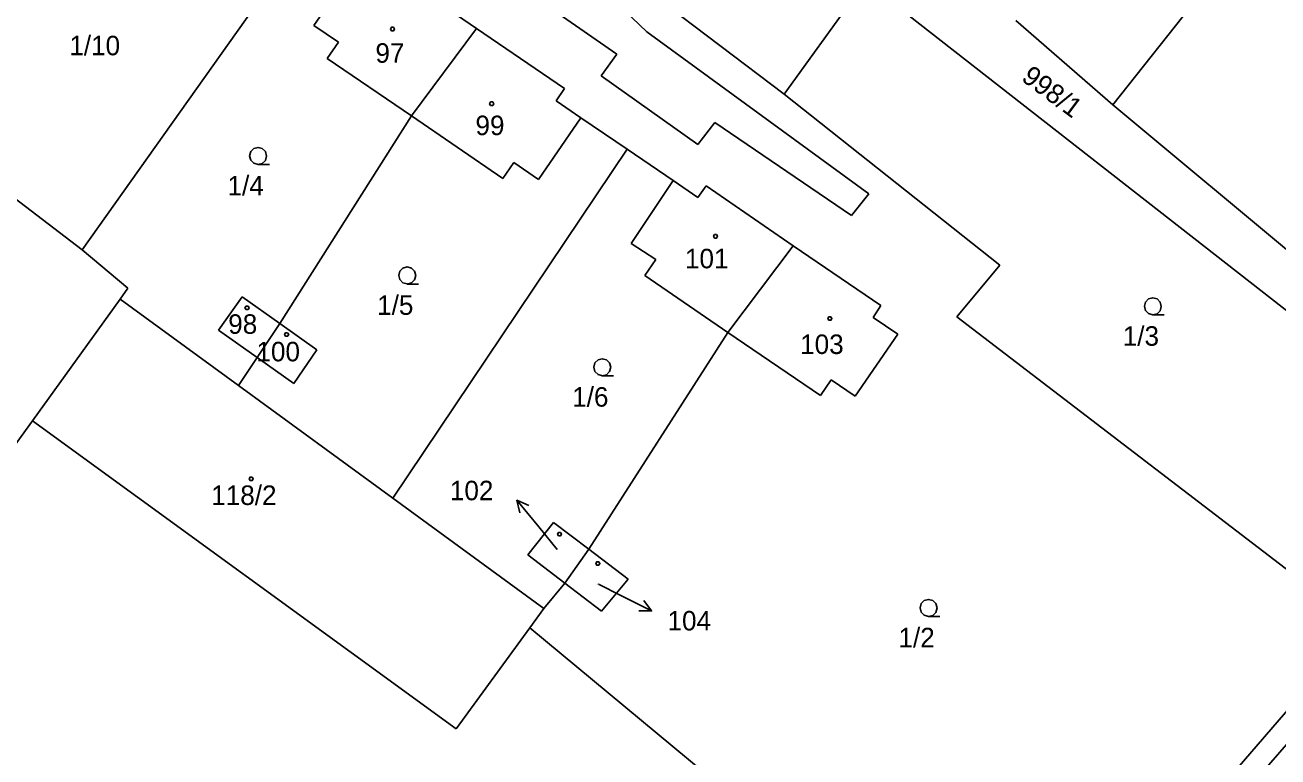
# Model space of a CAD drawing. Extents: x -852001 to -842497, y -1063614 to -1052182.
# Drawn here: x -849296.3 to -849187.1, y -1056403.5 to -1056339.7 of the extents above; entities that cross this region are included whole.
import ezdxf

# ---------------------------------------------------------------- set-up
doc = ezdxf.new("R2010")
doc.units = 0
for name, color, linetype in [('Default', 7, 'Continuous'), ('KN_HRANICE', 7, 'Continuous'), ('KN_KULTURY', 7, 'Continuous'), ('KN_PARCELY', 7, 'Continuous')]:
    doc.layers.add(name, color=color, linetype=linetype)

# ---------------------------------------------------------------- blocks, each defined once
blk = doc.blocks.new('304')
at = {"layer": 'Default'}
blk.add_lwpolyline([(0, 0), (-0.38, 0.1), (-0.65, 0.37), (-0.75, 0.74), (-0.65, 1.11), (-0.38, 1.38), (-0.01, 1.48), (0.36, 1.38), (0.63, 1.11), (0.73, 0.73), (0.63, 0.35), (0.36, 0.08), (-0.02, -0.02), (0.98, -0.02)], dxfattribs=at)
blk = doc.blocks.new('NAHRADNI_SYMBOL')
at = {"layer": 'Default'}
blk.add_lwpolyline([(0.09, 0.15), (0.18, 0), (0.09, -0.15), (-0.09, -0.15), (-0.18, 0), (-0.09, 0.15), (0.09, 0.15)], dxfattribs=at)
blk = doc.blocks.new('10292')
at = {"layer": 'Default'}
blk.add_line((0, 3), (0, 0), dxfattribs=at)
blk.add_lwpolyline([(-0.5, 2), (0, 3), (0.5, 2)], dxfattribs=at)
blk = doc.blocks.new('402')
at = {"layer": 'Default'}
blk.add_lwpolyline([(0.09, 0.15), (0.18, 0), (0.09, -0.15), (-0.09, -0.15), (-0.18, 0), (-0.09, 0.15), (0.09, 0.15)], dxfattribs=at)

msp = doc.modelspace()

# ---------------------------------------------------------------- linework, layer by layer
at = {"layer": 'KN_HRANICE'}
for p, q in [((-849201.5, -1056346.7), (-849181.26, -1056321.09)), ((-849201.5, -1056346.7), (-849181.26, -1056321.09)), ((-849291.34, -1056359.34), (-849271.64, -1056331.55)), ((-849291.34, -1056359.34), (-849271.64, -1056331.55)), ((-849244.73, -1056342.28), (-849259.75, -1056331.81)), ((-849244.73, -1056342.28), (-849259.75, -1056331.81)), ((-849267.48, -1056334.39), (-849271.16, -1056339.78)), ((-849267.48, -1056334.39), (-849271.16, -1056339.78)), ((-849249.23, -1056333.55), (-849242.11, -1056340.33)), ((-849249.23, -1056333.55), (-849242.11, -1056340.33)), ((-849230.16, -1056345.77), (-849246.19, -1056333.59)), ((-849230.16, -1056345.77), (-849246.19, -1056333.59)), ((-849264.6, -1056334.81), (-849256.96, -1056340.03)), ((-849264.6, -1056334.81), (-849256.96, -1056340.03)), ((-849223.07, -1056335.94), (-849230.16, -1056345.77)), ((-849223.07, -1056335.94), (-849230.16, -1056345.77)), ((-849223.07, -1056335.94), (-849168.88, -1056378.32)), ((-849223.07, -1056335.94), (-849168.88, -1056378.32)), ((-849271.16, -1056339.78), (-849269.01, -1056341.24)), ((-849271.16, -1056339.78), (-849269.01, -1056341.24)), ((-849201.5, -1056346.7), (-849209.96, -1056339.35)), ((-849201.5, -1056346.7), (-849209.96, -1056339.35)), ((-849262.65, -1056347.66), (-849256.96, -1056340.03)), ((-849262.65, -1056347.66), (-849256.96, -1056340.03)), ((-849256.96, -1056340.03), (-849249.3, -1056345.26)), ((-849256.96, -1056340.03), (-849249.3, -1056345.26)), ((-849242.11, -1056340.33), (-849222.76, -1056354.44)), ((-849242.11, -1056340.33), (-849222.76, -1056354.44)), ((-849269.01, -1056341.24), (-849269.98, -1056342.65)), ((-849269.01, -1056341.24), (-849269.98, -1056342.65)), ((-849269.98, -1056342.65), (-849262.65, -1056347.66)), ((-849269.98, -1056342.65), (-849262.65, -1056347.66)), ((-849246.11, -1056344.16), (-849244.73, -1056342.28)), ((-849246.11, -1056344.16), (-849244.73, -1056342.28)), ((-849237.68, -1056350.14), (-849246.11, -1056344.16)), ((-849237.68, -1056350.14), (-849246.11, -1056344.16)), ((-849250.02, -1056346.33), (-849249.3, -1056345.26)), ((-849250.02, -1056346.33), (-849249.3, -1056345.26)), ((-849247.87, -1056347.82), (-849250.02, -1056346.33)), ((-849247.87, -1056347.82), (-849250.02, -1056346.33)), ((-849230.16, -1056345.77), (-849211.36, -1056360.66)), ((-849230.16, -1056345.77), (-849211.36, -1056360.66)), ((-849201.5, -1056346.7), (-849166.49, -1056375.89)), ((-849201.5, -1056346.7), (-849166.49, -1056375.89)), ((-849262.65, -1056347.66), (-849274.12, -1056365.74)), ((-849262.65, -1056347.66), (-849274.12, -1056365.74)), ((-849262.65, -1056347.66), (-849254.67, -1056353.12)), ((-849262.65, -1056347.66), (-849254.67, -1056353.12)), ((-849251.57, -1056353.21), (-849247.87, -1056347.82)), ((-849251.57, -1056353.21), (-849247.87, -1056347.82)), ((-849243.84, -1056350.56), (-849247.87, -1056347.82)), ((-849243.84, -1056350.56), (-849247.87, -1056347.82)), ((-849236.2, -1056348.24), (-849237.68, -1056350.14)), ((-849236.2, -1056348.24), (-849237.68, -1056350.14)), ((-849224.27, -1056356.34), (-849236.2, -1056348.24)), ((-849224.27, -1056356.34), (-849236.2, -1056348.24)), ((-849264.25, -1056380.97), (-849243.84, -1056350.56)), ((-849264.25, -1056380.97), (-849243.84, -1056350.56)), ((-849243.84, -1056350.56), (-849239.82, -1056353.29)), ((-849243.84, -1056350.56), (-849239.82, -1056353.29)), ((-849254.67, -1056353.12), (-849253.72, -1056351.73)), ((-849254.67, -1056353.12), (-849253.72, -1056351.73)), ((-849253.72, -1056351.73), (-849251.57, -1056353.21)), ((-849253.72, -1056351.73), (-849251.57, -1056353.21)), ((-849291.34, -1056359.34), (-849299.09, -1056353.44)), ((-849291.34, -1056359.34), (-849299.09, -1056353.44)), ((-849239.82, -1056353.29), (-849243.49, -1056358.79)), ((-849239.82, -1056353.29), (-849243.49, -1056358.79)), ((-849237.67, -1056354.78), (-849239.82, -1056353.29)), ((-849237.67, -1056354.78), (-849239.82, -1056353.29)), ((-849236.96, -1056353.76), (-849237.67, -1056354.78)), ((-849236.96, -1056353.76), (-849237.67, -1056354.78)), ((-849229.36, -1056358.98), (-849236.96, -1056353.76)), ((-849229.36, -1056358.98), (-849236.96, -1056353.76)), ((-849222.76, -1056354.44), (-849224.27, -1056356.34)), ((-849222.76, -1056354.44), (-849224.27, -1056356.34)), ((-849287.35, -1056362.68), (-849291.34, -1056359.34)), ((-849287.35, -1056362.68), (-849291.34, -1056359.34)), ((-849243.49, -1056358.79), (-849241.35, -1056360.18)), ((-849243.49, -1056358.79), (-849241.35, -1056360.18)), ((-849235.05, -1056366.54), (-849229.36, -1056358.98)), ((-849235.05, -1056366.54), (-849229.36, -1056358.98)), ((-849221.74, -1056364.19), (-849229.36, -1056358.98)), ((-849221.74, -1056364.19), (-849229.36, -1056358.98)), ((-849241.35, -1056360.18), (-849242.29, -1056361.57)), ((-849241.35, -1056360.18), (-849242.29, -1056361.57)), ((-849211.36, -1056360.66), (-849215.1, -1056365.17)), ((-849211.36, -1056360.66), (-849215.1, -1056365.17)), ((-849242.29, -1056361.57), (-849235.05, -1056366.54)), ((-849242.29, -1056361.57), (-849235.05, -1056366.54)), ((-849288.04, -1056363.64), (-849287.35, -1056362.68)), ((-849288.04, -1056363.64), (-849287.35, -1056362.68)), ((-849288.04, -1056363.64), (-849295.68, -1056374.24)), ((-849288.04, -1056363.64), (-849295.68, -1056374.24)), ((-849277.71, -1056371.17), (-849288.04, -1056363.64)), ((-849277.71, -1056371.17), (-849288.04, -1056363.64)), ((-849277.39, -1056363.43), (-849279.45, -1056366.33)), ((-849277.39, -1056363.43), (-849279.45, -1056366.33)), ((-849274.12, -1056365.74), (-849277.39, -1056363.43)), ((-849274.12, -1056365.74), (-849277.39, -1056363.43)), ((-849221.74, -1056364.19), (-849222.41, -1056365.22)), ((-849221.74, -1056364.19), (-849222.41, -1056365.22)), ((-849274.12, -1056365.74), (-849276.09, -1056368.72)), ((-849274.12, -1056365.74), (-849276.09, -1056368.72)), ((-849270.88, -1056368.05), (-849274.12, -1056365.74)), ((-849270.88, -1056368.05), (-849274.12, -1056365.74)), ((-849222.41, -1056365.22), (-849220.26, -1056366.67)), ((-849222.41, -1056365.22), (-849220.26, -1056366.67)), ((-849215.1, -1056365.17), (-849179.95, -1056392.09)), ((-849215.1, -1056365.17), (-849179.95, -1056392.09)), ((-849279.45, -1056366.33), (-849276.09, -1056368.72)), ((-849279.45, -1056366.33), (-849276.09, -1056368.72)), ((-849235.05, -1056366.54), (-849247.17, -1056385.43)), ((-849235.05, -1056366.54), (-849247.17, -1056385.43)), ((-849235.05, -1056366.54), (-849227, -1056372.04)), ((-849235.05, -1056366.54), (-849227, -1056372.04)), ((-849220.26, -1056366.67), (-849223.96, -1056372.1)), ((-849220.26, -1056366.67), (-849223.96, -1056372.1)), ((-849272.9, -1056370.99), (-849270.88, -1056368.05)), ((-849272.9, -1056370.99), (-849270.88, -1056368.05)), ((-849276.09, -1056368.72), (-849277.71, -1056371.17)), ((-849276.09, -1056368.72), (-849277.71, -1056371.17)), ((-849276.09, -1056368.72), (-849272.9, -1056370.99)), ((-849276.09, -1056368.72), (-849272.9, -1056370.99)), ((-849264.25, -1056380.97), (-849277.71, -1056371.17)), ((-849264.25, -1056380.97), (-849277.71, -1056371.17)), ((-849226.06, -1056370.67), (-849227, -1056372.04)), ((-849226.06, -1056370.67), (-849227, -1056372.04)), ((-849223.96, -1056372.1), (-849226.06, -1056370.67)), ((-849223.96, -1056372.1), (-849226.06, -1056370.67)), ((-849295.68, -1056374.24), (-849308.52, -1056391.92)), ((-849295.68, -1056374.24), (-849308.52, -1056391.92)), ((-849258.75, -1056401.09), (-849295.68, -1056374.24)), ((-849258.75, -1056401.09), (-849295.68, -1056374.24)), ((-849207.62, -1056426.96), (-849167.05, -1056380.13)), ((-849207.62, -1056426.96), (-849167.05, -1056380.13)), ((-849251.09, -1056390.6), (-849264.25, -1056380.97)), ((-849251.09, -1056390.6), (-849264.25, -1056380.97)), ((-849252.49, -1056385.93), (-849250.27, -1056383.09)), ((-849252.49, -1056385.93), (-849250.27, -1056383.09)), ((-849250.27, -1056383.09), (-849247.17, -1056385.43)), ((-849250.27, -1056383.09), (-849247.17, -1056385.43)), ((-849249.26, -1056388.39), (-849247.17, -1056385.43)), ((-849249.26, -1056388.39), (-849247.17, -1056385.43)), ((-849247.17, -1056385.43), (-849243.74, -1056388.04)), ((-849247.17, -1056385.43), (-849243.74, -1056388.04)), ((-849249.26, -1056388.39), (-849252.49, -1056385.93)), ((-849249.26, -1056388.39), (-849252.49, -1056385.93)), ((-849251.09, -1056390.6), (-849249.26, -1056388.39)), ((-849251.09, -1056390.6), (-849249.26, -1056388.39)), ((-849246.07, -1056390.82), (-849249.26, -1056388.39)), ((-849246.07, -1056390.82), (-849249.26, -1056388.39)), ((-849243.74, -1056388.04), (-849246.07, -1056390.82)), ((-849243.74, -1056388.04), (-849246.07, -1056390.82)), ((-849252.32, -1056392.28), (-849251.09, -1056390.6)), ((-849252.32, -1056392.28), (-849251.09, -1056390.6)), ((-849258.75, -1056401.09), (-849252.32, -1056392.28)), ((-849258.75, -1056401.09), (-849252.32, -1056392.28)), ((-849252.32, -1056392.28), (-849210.21, -1056427.21)), ((-849252.32, -1056392.28), (-849210.21, -1056427.21)), ((-849210.21, -1056427.21), (-849179.95, -1056392.09)), ((-849210.21, -1056427.21), (-849179.95, -1056392.09))]:
    msp.add_line(p, q, dxfattribs=at)
at = {"layer": 'KN_PARCELY'}
for p, q in [((-849249.93, -1056385.45), (-849251.54, -1056383.48)), ((-849249.93, -1056385.45), (-849251.54, -1056383.48)), ((-849246.35, -1056388.48), (-849244.39, -1056389.46)), ((-849246.35, -1056388.48), (-849244.39, -1056389.46))]:
    msp.add_line(p, q, dxfattribs=at)

# ---------------------------------------------------------------- block references
at = {"layer": 'KN_KULTURY'}
for name, p in [('402', (-849264.29, -1056340.08)), ('402', (-849264.29, -1056340.08)), ('402', (-849255.65, -1056346.59)), ('402', (-849255.65, -1056346.59)), ('304', (-849276, -1056351.88)), ('304', (-849276, -1056351.88)), ('402', (-849236.13, -1056358.15)), ('402', (-849236.13, -1056358.15)), ('304', (-849263, -1056362.3)), ('304', (-849263, -1056362.3)), ('304', (-849198.01, -1056364.99)), ('304', (-849198.01, -1056364.99)), ('402', (-849276.97, -1056364.39)), ('402', (-849276.97, -1056364.39)), ('402', (-849226.17, -1056365.32)), ('402', (-849226.17, -1056365.32)), ('402', (-849273.52, -1056366.71)), ('402', (-849273.52, -1056366.71)), ('304', (-849246, -1056370.3)), ('304', (-849246, -1056370.3)), ('NAHRADNI_SYMBOL', (-849276.61, -1056379.29)), ('NAHRADNI_SYMBOL', (-849276.61, -1056379.29)), ('402', (-849249.73, -1056384.11)), ('402', (-849249.73, -1056384.11)), ('402', (-849246.4, -1056386.67)), ('402', (-849246.4, -1056386.67)), ('304', (-849217.56, -1056391.28)), ('304', (-849217.56, -1056391.28))]:
    msp.add_blockref(name, p, dxfattribs=at)
at = {"layer": 'KN_PARCELY'}
for p, rotation in [((-849251.54, -1056383.48), 39.304905), ((-849251.54, -1056383.48), 39.304905), ((-849244.39, -1056389.46), -116.66482400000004), ((-849244.39, -1056389.46), -116.66482400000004)]:
    msp.add_blockref('10292', p, dxfattribs=dict(at, rotation=rotation))

# ---------------------------------------------------------------- texts
for s, height, p in [('1/10', 1.7, (-849292.46, -1056342.37)), ('1/10', 1.7, (-849292.46, -1056342.37)), ('97', 1.7, (-849265.78, -1056343.02)), ('97', 1.7, (-849265.78, -1056343.02)), ('99', 1.7, (-849257.06, -1056349.33)), ('99', 1.7, (-849257.06, -1056349.33)), ('1/4', 1.7, (-849278.67, -1056354.58)), ('1/4', 1.7, (-849278.67, -1056354.58)), ('101', 1.7, (-849238.8, -1056360.94)), ('101', 1.7, (-849238.8, -1056360.94)), ('1/5', 1.7, (-849265.63, -1056365)), ('1/5', 1.7, (-849265.63, -1056365)), ('98', 1.7, (-849278.61, -1056366.65)), ('98', 1.7, (-849278.61, -1056366.65)), ('1/3', 1.7, (-849200.64, -1056367.69)), ('1/3', 1.7, (-849200.64, -1056367.69)), ('103', 1.7, (-849228.76, -1056368.41)), ('103', 1.7, (-849228.76, -1056368.41)), ('100', 1.7, (-849276.15, -1056369.05)), ('100', 1.7, (-849276.15, -1056369.05)), ('1/6', 1.7, (-849248.63, -1056373)), ('1/6', 1.7, (-849248.63, -1056373)), ('118/2', 1.7, (-849280.09, -1056381.57)), ('118/2', 1.7, (-849280.09, -1056381.57)), ('102', 1.7, (-849259.29, -1056381.16)), ('102', 1.7, (-849259.29, -1056381.16)), ('102', 0.1, (-849250.08, -1056385.45)), ('102', 0.1, (-849250.08, -1056385.45)), ('104', 0.1, (-849246.5, -1056388.48)), ('104', 0.1, (-849246.5, -1056388.48)), ('104', 1.7, (-849240.32, -1056392.51)), ('104', 1.7, (-849240.32, -1056392.51)), ('1/2', 1.7, (-849220.19, -1056393.98)), ('1/2', 1.7, (-849220.19, -1056393.98))]:
    msp.add_text(s, height=height, dxfattribs=at).set_placement(p)
msp.add_text('998/1', height=1.7, rotation=323.205, dxfattribs=at).set_placement((-849209.57, -1056344.51))
msp.add_text('998/1', height=1.7, rotation=323.205, dxfattribs=at).set_placement((-849209.57, -1056344.51))

doc.saveas('drawing.dxf')
